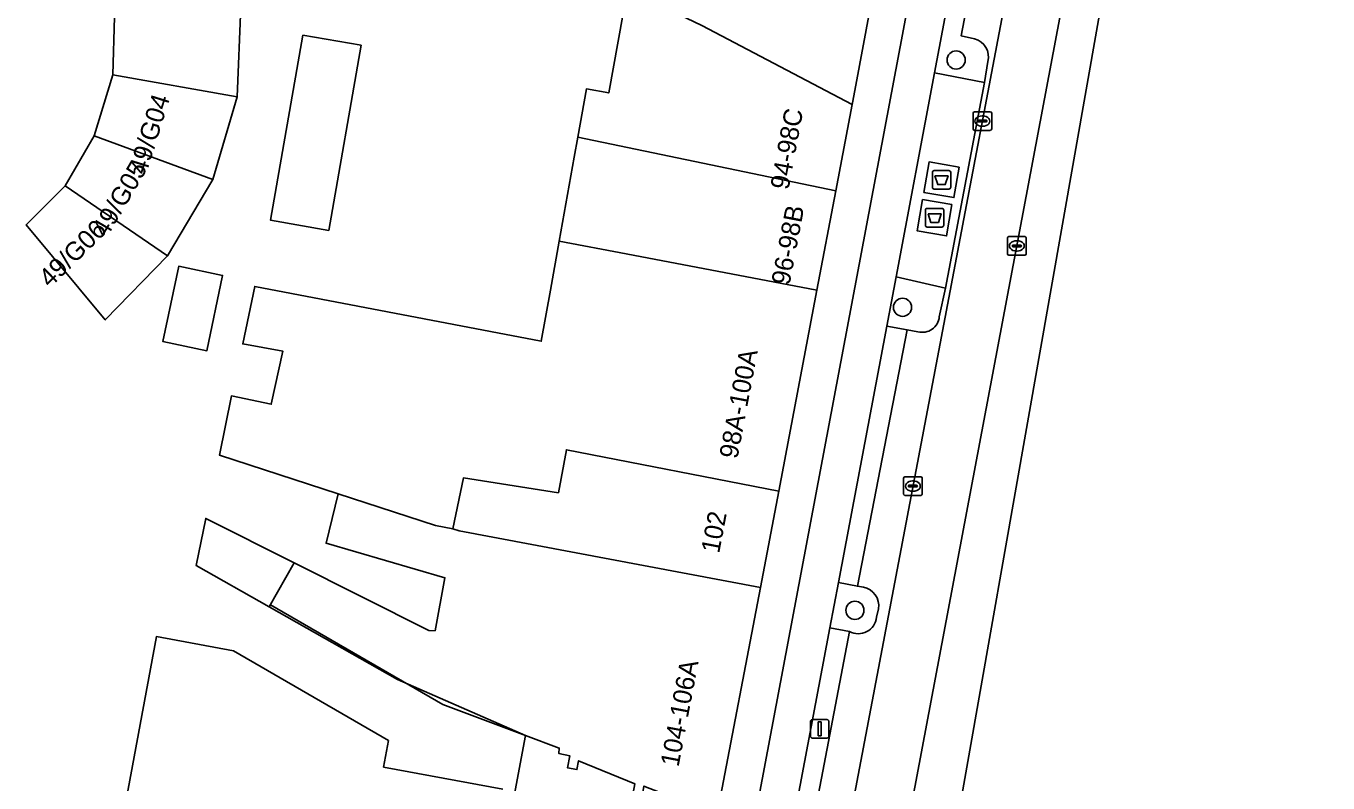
# Model space of a CAD drawing. Extents: x 161402 to 161933, y 381647 to 382315.
# Drawn here: x 161821 to 161891.1, y 381796.3 to 381837.1 of the extents above; entities that cross this region are included whole.
import ezdxf

# ---------------------------------------------------------------- set-up
doc = ezdxf.new("R2010")
doc.units = 0
for name, color, linetype in [('IMGEO_Afval_apart_plaats', 7, 'Continuous'), ('IMGEO_Berm_groen', 7, 'Continuous'), ('IMGEO_Berm_open', 7, 'Continuous'), ('IMGEO_Boom', 7, 'Continuous'), ('IMGEO_Erf', 7, 'Continuous'), ('IMGEO_Fietspad_gesloten', 7, 'Continuous'), ('IMGEO_Hek', 7, 'Continuous'), ('IMGEO_Kolk', 7, 'Continuous'), ('IMGEO_Lichtmast', 7, 'Continuous'), ('IMGEO_OVBaan_gesloten', 7, 'Continuous'), ('IMGEO_Pand', 7, 'Continuous'), ('IMGEO_Pand_nummerreeks', 7, 'Continuous'), ('IMGEO_Pand_overbouw', 7, 'Continuous'), ('IMGEO_Parkeervlak_open', 7, 'Continuous'), ('IMGEO_Rijbaan_lokaal_gesloten', 7, 'Continuous'), ('IMGEO_Rioolput', 7, 'Continuous'), ('IMGEO_Verkeerseiland_open', 7, 'Continuous'), ('IMGEO_Voetpad_gesloten', 7, 'Continuous'), ('IMGEO_Voetpad_open', 7, 'Continuous')]:
    doc.layers.add(name, color=color, linetype=linetype)

msp = doc.modelspace()

# ---------------------------------------------------------------- linework, layer by layer
at = {"layer": 'IMGEO_Afval_apart_plaats'}
for p, q in [((161869.774, 381828.434), (161869.774, 381829.234)), ((161869.774, 381829.234), (161869.774, 381828.434)), ((161869.874, 381829.334), (161870.664, 381829.334)), ((161870.664, 381829.334), (161869.874, 381829.334)), ((161870.764, 381829.234), (161870.764, 381828.434)), ((161870.764, 381828.434), (161870.764, 381829.234)), ((161870.664, 381828.334), (161869.874, 381828.334)), ((161869.874, 381828.334), (161870.664, 381828.334)), ((161869.4, 381826.391), (161869.4, 381827.191)), ((161869.4, 381827.191), (161869.4, 381826.391)), ((161869.5, 381827.291), (161870.29, 381827.291)), ((161870.29, 381827.291), (161869.5, 381827.291)), ((161870.39, 381827.191), (161870.39, 381826.391)), ((161870.39, 381826.391), (161870.39, 381827.191)), ((161870.29, 381826.291), (161869.5, 381826.291)), ((161869.5, 381826.291), (161870.29, 381826.291))]:
    msp.add_line(p, q, dxfattribs=at)
for points in [[(161869.917, 381829.048), (161870.621, 381829.048), (161870.472, 381828.578), (161870.066, 381828.578), (161869.917, 381829.048)], [(161869.543, 381827.005), (161870.247, 381827.005), (161870.098, 381826.535), (161869.692, 381826.535), (161869.543, 381827.005)]]:
    msp.add_lwpolyline(points, dxfattribs=at)
for centre, start, end in [((161869.874, 381829.234), 90, 180), ((161869.874, 381829.234), 90, 180), ((161870.664, 381829.234), 0, 90), ((161870.664, 381829.234), 360, 90), ((161869.874, 381828.434), 180, 270), ((161869.874, 381828.434), 180, 270), ((161870.664, 381828.434), 270, 0), ((161870.664, 381828.434), 270, 0), ((161869.5, 381827.191), 90, 180), ((161869.5, 381827.191), 90, 180), ((161870.29, 381827.191), 0, 90), ((161870.29, 381827.191), 360, 90), ((161869.5, 381826.391), 180, 270), ((161869.5, 381826.391), 180, 270), ((161870.29, 381826.391), 270, 0), ((161870.29, 381826.391), 270, 0)]:
    msp.add_arc(centre, 0.1, start, end, dxfattribs=at)
at = {"layer": 'IMGEO_Berm_groen'}
for points in [[(161870.482, 381822.992), (161867.824, 381823.608), (161867.323, 381820.954), (161868.41, 381820.749), (161868.995, 381820.652)], [(161870.147, 381821.456), (161870.482, 381822.992)], [(161866.06, 381806.892), (161865.742, 381806.939), (161864.714, 381807.133), (161864.254, 381804.698), (161865.316, 381804.498)], [(161866.768, 381805.264), (161866.881, 381805.727)]]:
    msp.add_lwpolyline(points, dxfattribs=at)
for centre, radius, start, end in [((161869.235, 381821.536), 0.916, 254.82541, 354.99825), ((161865.846, 381805.869), 1.045, 352.18385, 78.16247), ((161865.789, 381805.36), 0.983, 241.21658, 354.41103)]:
    msp.add_arc(centre, radius, start, end, dxfattribs=at)
at = {"layer": 'IMGEO_Berm_open'}
msp.add_lwpolyline([(161868.41, 381820.749), (161867.323, 381820.954), (161864.714, 381807.133), (161865.742, 381806.939)], close=True, dxfattribs=at)
msp.add_lwpolyline([(161855.069, 381750), (161856.164, 381755.911), (161857.682, 381764.091), (161858.781, 381770.01), (161859.554, 381774.178), (161860.503, 381779.34), (161860.529, 381779.475), (161865.316, 381804.498), (161864.254, 381804.698), (161859.509, 381779.56), (161854.016, 381750), (161850.643, 381731.85), (161849.541, 381725.922), (161844.249, 381697.445)], dxfattribs=at)
at = {"layer": 'IMGEO_Boom'}
for centre in [(161871.055, 381835.287), (161868.169, 381821.967), (161865.604, 381805.641)]:
    msp.add_circle(centre, 0.489, dxfattribs=at)
at = {"layer": 'IMGEO_Erf'}
for points in [[(161825.632, 381834.487), (161825.716, 381837.606), (161825.13, 381840.815), (161823.801, 381843.856), (161829.804, 381847.078), (161831.717, 381842.638), (161832.532, 381838.148), (161832.326, 381833.3), (161831.022, 381828.853), (161828.579, 381824.737), (161825.227, 381821.282), (161820.956, 381826.404), (161823.067, 381828.511), (161824.629, 381831.199)], [(161835.87, 381836.631), (161839.006, 381836.083), (161837.262, 381826.104), (161834.125, 381826.652)], [(161829.182, 381824.176), (161831.547, 381823.681), (161830.698, 381819.624), (161828.333, 381820.119)]]:
    msp.add_lwpolyline(points, close=True, dxfattribs=at)
for points in [[(161853.746, 381796.3), (161850.716, 381797.533), (161850.627, 381797.062), (161850.117, 381797.158), (161850.239, 381797.804), (161849.663, 381797.923), (161849.682, 381798.222), (161847.86, 381798.902), (161840.962, 381801.911), (161834.057, 381805.821), (161830.124, 381808.048), (161830.633, 381810.59), (161835.39, 381808.201), (161842.647, 381804.557), (161842.986, 381804.544), (161843.522, 381807.394), (161837.118, 381809.253), (161837.762, 381811.919), (161831.384, 381813.997), (161832.023, 381817.194), (161834.166, 381816.745), (161834.791, 381819.599), (161832.631, 381819.995), (161833.279, 381823.092), (161845.982, 381820.657), (161848.712, 381820.134), (161849.205, 381822.897), (161849.676, 381825.535), (161850.483, 381830.049), (161850.676, 381831.127), (161851.141, 381833.729), (161852.346, 381833.514), (161853.347, 381839.11)], [(161825.253, 381789.517), (161827.976, 381804.229), (161832.124, 381803.461), (161840.482, 381798.624), (161840.218, 381797.195), (161846.644, 381796.006)]]:
    msp.add_lwpolyline(points, dxfattribs=at)
at = {"layer": 'IMGEO_Fietspad_gesloten'}
for points in [[(161910.061, 382061.001), (161905.702, 382037.375), (161898.752, 382000), (161887.89, 381941.593), (161886.669, 381935.154), (161880.56, 381902.497), (161879.486, 381896.758), (161857.65, 381780.798), (161851.928, 381750), (161842.232, 381697.819)], [(161844.249, 381697.445), (161849.541, 381725.922), (161850.643, 381731.85), (161854.016, 381750), (161859.509, 381779.56), (161864.254, 381804.698), (161864.714, 381807.133), (161867.323, 381820.954), (161867.824, 381823.608), (161869.899, 381834.602), (161881.54, 381896.271)]]:
    msp.add_lwpolyline(points, dxfattribs=at)
at = {"layer": 'IMGEO_Hek'}
msp.add_lwpolyline([(161847.86, 381798.902), (161843.405, 381800.565), (161834.122, 381805.937)], dxfattribs=at)
at = {"layer": 'IMGEO_Kolk'}
for p, q in [((161871.971, 381831.573), (161871.971, 381832.425)), ((161872.046, 381832.499), (161872.898, 381832.499)), ((161872.23, 381831.993), (161872.23, 381832.005)), ((161872.668, 381831.956), (161872.27, 381831.956)), ((161872.273, 381832.042), (161872.671, 381832.042)), ((161872.459, 381832.279), (161872.484, 381832.279)), ((161872.714, 381832.005), (161872.714, 381831.993)), ((161872.972, 381832.425), (161872.972, 381831.573)), ((161872.898, 381831.499), (161872.046, 381831.499)), ((161872.482, 381831.719), (161872.457, 381831.719)), ((161868.225, 381811.906), (161868.225, 381812.758)), ((161868.3, 381812.832), (161869.152, 381812.832)), ((161868.484, 381812.326), (161868.484, 381812.338)), ((161868.922, 381812.289), (161868.524, 381812.289)), ((161868.527, 381812.375), (161868.925, 381812.375)), ((161868.713, 381812.612), (161868.738, 381812.612)), ((161868.968, 381812.338), (161868.968, 381812.326)), ((161869.226, 381812.758), (161869.226, 381811.906)), ((161869.152, 381811.832), (161868.3, 381811.832)), ((161868.736, 381812.052), (161868.711, 381812.052))]:
    msp.add_line(p, q, dxfattribs=at)
for points in [[(161871.971, 381831.573), (161871.971, 381832.425)], [(161872.046, 381832.499), (161872.898, 381832.499)], [(161872.972, 381832.425), (161872.972, 381831.573)], [(161872.898, 381831.499), (161872.046, 381831.499)], [(161868.225, 381811.906), (161868.225, 381812.758)], [(161868.3, 381812.832), (161869.152, 381812.832)], [(161869.226, 381812.758), (161869.226, 381811.906)], [(161869.152, 381811.832), (161868.3, 381811.832)]]:
    msp.add_lwpolyline(points, dxfattribs=at)
for centre, radius, start, end in [((161872.048, 381832.423), 0.0765, 91.55205, 178.44795), ((161872.048, 381832.423), 0.0765, 91.55205, 178.44795), ((161872.27, 381832.002), 0.0403, 85.87752, 175.75265), ((161872.267, 381831.992), 0.0366, 178.93798, 274.71019), ((161872.671, 381831.999), 0.043, 264.86636, 352.45326), ((161872.675, 381832.004), 0.0386, 1.73085, 96.63898), ((161872.896, 381832.423), 0.0765, 1.55205, 88.44795), ((161872.896, 381832.423), 0.0765, 1.55205, 88.44795), ((161872.048, 381831.575), 0.0765, 181.55205, 268.44795), ((161872.048, 381831.575), 0.0765, 181.55205, 268.44795), ((161872.896, 381831.575), 0.0765, 271.55205, 358.44795), ((161872.896, 381831.575), 0.0765, 271.55205, 358.44795), ((161868.302, 381812.756), 0.0765, 91.55205, 178.44795), ((161868.302, 381812.756), 0.0765, 91.55205, 178.44795), ((161868.524, 381812.335), 0.0403, 85.87752, 175.75265), ((161868.521, 381812.325), 0.0366, 178.93798, 274.71019), ((161868.925, 381812.332), 0.043, 264.86636, 352.45326), ((161868.929, 381812.337), 0.0386, 1.73085, 96.63898), ((161869.15, 381812.756), 0.0765, 1.55205, 88.44795), ((161869.15, 381812.756), 0.0765, 1.55205, 88.44795), ((161868.302, 381811.908), 0.0765, 181.55205, 268.44795), ((161868.302, 381811.908), 0.0765, 181.55205, 268.44795), ((161869.15, 381811.908), 0.0765, 271.55205, 358.44795), ((161869.15, 381811.908), 0.0765, 271.55205, 358.44795)]:
    msp.add_arc(centre, radius, start, end, dxfattribs=at)
for centre, major_axis, ratio, start_param, end_param in [((161872.458, 381831.999), (-0.387, 0.002), 0.722429, 4.712389, 7.853982), ((161872.483, 381831.999), (-0.39, 0.002), 0.717154, 1.570796, 4.712389), ((161868.712, 381812.332), (-0.387, 0.002), 0.722429, 4.712389, 7.853982), ((161868.737, 381812.332), (-0.39, 0.002), 0.717154, 1.570796, 4.712389)]:
    msp.add_ellipse(centre, major_axis=major_axis, ratio=ratio, start_param=start_param, end_param=end_param, dxfattribs=at)
at = {"layer": 'IMGEO_Lichtmast'}
for p, q in [((161863.21, 381798.856), (161863.21, 381799.656)), ((161863.21, 381799.656), (161863.21, 381798.856)), ((161863.31, 381799.756), (161864.1, 381799.756)), ((161864.1, 381799.756), (161863.31, 381799.756)), ((161864.2, 381799.656), (161864.2, 381798.856)), ((161864.2, 381798.856), (161864.2, 381799.656)), ((161864.1, 381798.756), (161863.31, 381798.756)), ((161863.31, 381798.756), (161864.1, 381798.756))]:
    msp.add_line(p, q, dxfattribs=at)
msp.add_lwpolyline([(161863.63, 381799.631), (161863.78, 381799.631), (161863.78, 381798.881), (161863.63, 381798.881), (161863.63, 381799.631)], dxfattribs=at)
for centre, start, end in [((161863.31, 381799.656), 90, 180), ((161863.31, 381799.656), 90, 180), ((161864.1, 381799.656), 0, 90), ((161864.1, 381799.656), 360, 90), ((161863.31, 381798.856), 180, 270), ((161863.31, 381798.856), 180, 270), ((161864.1, 381798.856), 270, 0), ((161864.1, 381798.856), 270, 0)]:
    msp.add_arc(centre, 0.1, start, end, dxfattribs=at)
at = {"layer": 'IMGEO_OVBaan_gesloten'}
for points in [[(161847.327, 381677.629), (161847.814, 381679.325), (161869.795, 381786.79), (161883.773, 381866.122), (161911.481, 382007.357), (161916.93, 382035.129), (161933.101, 382124.399), (161931.462, 382125.963), (161930.949, 382121.39)], [(161929.574, 382113.249), (161927.659, 382104.365), (161926.989, 382101.276), (161926.695, 382099.95), (161920.797, 382074.121), (161920.568, 382072.989), (161920.066, 382070.485), (161894.174, 381930.698), (161894.155, 381930.593), (161893.956, 381929.536), (161893.492, 381927.072), (161889.963, 381908.334), (161866.208, 381782.197), (161866.199, 381782.149), (161865.069, 381776.053), (161864.537, 381773.18), (161864.311, 381771.961), (161856.328, 381728.885)]]:
    msp.add_lwpolyline(points, dxfattribs=at)
at = {"layer": 'IMGEO_Pand'}
for points in [[(161871.236, 381863.835), (161860.337, 381865.887), (161860.582, 381867.192), (161858.508, 381867.582), (161853.371, 381868.549), (161853.071, 381866.952), (161852.795, 381867.004), (161848.503, 381844.194), (161848.012, 381841.585), (161848.885, 381841.123), (161848.95, 381841.485), (161852.213, 381839.723), (161853.347, 381839.11), (161853.718, 381838.91), (161857.352, 381837.151), (161865.464, 381832.9), (161865.498, 381833.078)], [(161857.352, 381837.151), (161853.718, 381838.91), (161853.347, 381839.11), (161852.346, 381833.514), (161851.141, 381833.729), (161850.676, 381831.127), (161864.577, 381828.237), (161865.464, 381832.9)], [(161832.326, 381833.3), (161832.532, 381838.148), (161825.716, 381837.606), (161825.632, 381834.487)], [(161835.87, 381836.631), (161834.125, 381826.652), (161837.262, 381826.104), (161839.006, 381836.083)], [(161832.326, 381833.3), (161825.632, 381834.487), (161824.629, 381831.199), (161831.022, 381828.853)], [(161831.022, 381828.853), (161824.629, 381831.199), (161823.067, 381828.511), (161828.579, 381824.737)], [(161864.577, 381828.237), (161850.676, 381831.127), (161850.483, 381830.049), (161849.676, 381825.535), (161853.274, 381824.851), (161863.56, 381822.895)], [(161823.067, 381828.511), (161820.956, 381826.404), (161825.227, 381821.282), (161828.579, 381824.737)], [(161863.56, 381822.895), (161853.274, 381824.851), (161849.676, 381825.535), (161849.205, 381822.897), (161848.712, 381820.134), (161845.982, 381820.657), (161833.279, 381823.092), (161832.631, 381819.995), (161834.791, 381819.599), (161834.166, 381816.745), (161832.023, 381817.194), (161831.384, 381813.997), (161837.762, 381811.919), (161843.015, 381810.207), (161843.941, 381810.032), (161844.516, 381812.77), (161849.633, 381811.975), (161850.068, 381814.292), (161861.5, 381812.067)], [(161828.333, 381820.119), (161830.698, 381819.624), (161831.547, 381823.681), (161829.182, 381824.176)], [(161843.941, 381810.032), (161844.279, 381809.92), (161860.511, 381806.869), (161861.5, 381812.067), (161850.068, 381814.292), (161849.633, 381811.975), (161844.516, 381812.77)], [(161830.633, 381810.59), (161830.124, 381808.048), (161834.057, 381805.821), (161835.39, 381808.201)]]:
    msp.add_lwpolyline(points, close=True, dxfattribs=at)
for points in [[(161858.21, 381794.775), (161860.511, 381806.869), (161844.279, 381809.92), (161843.941, 381810.032), (161843.015, 381810.207), (161837.762, 381811.919), (161837.118, 381809.253), (161843.522, 381807.394), (161842.986, 381804.544), (161842.647, 381804.557), (161835.39, 381808.201), (161834.057, 381805.821), (161840.962, 381801.911), (161847.86, 381798.902), (161849.682, 381798.222), (161849.663, 381797.923), (161850.239, 381797.804), (161850.117, 381797.158), (161850.627, 381797.062), (161850.716, 381797.533), (161853.746, 381796.3)], [(161846.644, 381796.006), (161840.218, 381797.195), (161840.482, 381798.624), (161832.124, 381803.461), (161827.976, 381804.229), (161825.253, 381789.517)]]:
    msp.add_lwpolyline(points, dxfattribs=at)
at = {"layer": 'IMGEO_Pand_overbouw'}
msp.add_lwpolyline([(161857.009, 381789.446), (161858.115, 381794.262), (161857.427, 381794.392), (161857.521, 381794.895), (161854.239, 381796.167), (161854.154, 381795.713), (161853.653, 381795.807), (161853.746, 381796.3), (161850.716, 381797.533), (161850.627, 381797.062), (161850.117, 381797.158), (161850.239, 381797.804), (161849.663, 381797.923), (161849.682, 381798.222), (161847.86, 381798.902), (161847.248, 381795.649), (161851.239, 381794.077), (161851.163, 381793.987), (161851.433, 381793.88), (161856.08, 381792.037), (161856.9, 381790.844), (161856.653, 381789.512)], close=True, dxfattribs=at)
at = {"layer": 'IMGEO_Parkeervlak_open'}
for points in [[(161865.316, 381804.498), (161860.529, 381779.475), (161861.521, 381781.789), (161862.376, 381783.945), (161863.081, 381785.029), (161863.613, 381786.178), (161864.093, 381787.863), (161884.15, 381893.504)], [(161873.66, 381847.251), (161873.371, 381847.295), (161871.323, 381836.592), (161872.047, 381836.423)], [(161872.769, 381835.211), (161872.587, 381834.08), (161870.482, 381822.992), (161870.147, 381821.456)], [(161868.995, 381820.652), (161868.41, 381820.749), (161865.742, 381806.939), (161866.06, 381806.892)], [(161866.881, 381805.727), (161866.768, 381805.264)]]:
    msp.add_lwpolyline(points, dxfattribs=at)
for centre, radius, start, end in [((161871.795, 381835.452), 1.004, 346.1316, 75.43372), ((161869.235, 381821.536), 0.916, 254.82541, 354.99825), ((161865.846, 381805.869), 1.045, 352.18385, 78.16247), ((161865.789, 381805.36), 0.983, 241.21658, 354.41103)]:
    msp.add_arc(centre, radius, start, end, dxfattribs=at)
at = {"layer": 'IMGEO_Rijbaan_lokaal_gesloten'}
for points in [[(161866.208, 381782.197), (161889.963, 381908.334)], [(161884.17, 381893.607), (161884.15, 381893.504), (161864.093, 381787.863), (161863.613, 381786.178), (161863.081, 381785.029), (161862.376, 381783.945), (161861.521, 381781.789), (161860.529, 381779.475), (161860.503, 381779.34), (161859.554, 381774.178), (161858.781, 381770.01), (161857.682, 381764.091), (161856.164, 381755.911), (161855.069, 381750), (161851.669, 381731.66), (161850.569, 381725.731), (161845.879, 381700.449), (161845.656, 381699.227), (161845.077, 381696.29), (161841.891, 381681.821), (161841.621, 381680.659), (161841.162, 381678.679), (161840.43, 381675.643), (161840.392, 381675.483)]]:
    msp.add_lwpolyline(points, dxfattribs=at)
at = {"layer": 'IMGEO_Rioolput'}
for p, q in [((161873.826, 381824.847), (161873.826, 381825.699)), ((161873.901, 381825.773), (161874.753, 381825.773)), ((161874.314, 381825.553), (161874.339, 381825.553)), ((161874.827, 381825.699), (161874.827, 381824.847)), ((161874.085, 381825.267), (161874.085, 381825.279)), ((161874.523, 381825.23), (161874.125, 381825.23)), ((161874.128, 381825.316), (161874.526, 381825.316)), ((161874.337, 381824.993), (161874.312, 381824.993)), ((161874.569, 381825.279), (161874.569, 381825.267)), ((161874.753, 381824.773), (161873.901, 381824.773))]:
    msp.add_line(p, q, dxfattribs=at)
for points in [[(161873.826, 381824.847), (161873.826, 381825.699)], [(161873.901, 381825.773), (161874.753, 381825.773)], [(161874.827, 381825.699), (161874.827, 381824.847)], [(161874.753, 381824.773), (161873.901, 381824.773)]]:
    msp.add_lwpolyline(points, dxfattribs=at)
for centre, radius, start, end in [((161873.903, 381825.697), 0.0765, 91.55205, 178.44795), ((161873.903, 381825.697), 0.0765, 91.55205, 178.44795), ((161874.751, 381825.697), 0.0765, 1.55205, 88.44795), ((161874.751, 381825.697), 0.0765, 1.55205, 88.44795), ((161873.903, 381824.849), 0.0765, 181.55205, 268.44795), ((161873.903, 381824.849), 0.0765, 181.55205, 268.44795), ((161874.125, 381825.276), 0.0403, 85.87752, 175.75265), ((161874.122, 381825.266), 0.0366, 178.93798, 274.71019), ((161874.526, 381825.273), 0.043, 264.86636, 352.45326), ((161874.53, 381825.278), 0.0386, 1.73085, 96.63898), ((161874.751, 381824.849), 0.0765, 271.55205, 358.44795), ((161874.751, 381824.849), 0.0765, 271.55205, 358.44795)]:
    msp.add_arc(centre, radius, start, end, dxfattribs=at)
for centre, major_axis, ratio, start_param, end_param in [((161874.313, 381825.273), (-0.387, 0.002), 0.722429, 4.712389, 7.853982), ((161874.338, 381825.273), (-0.39, 0.002), 0.717154, 1.570796, 4.712389)]:
    msp.add_ellipse(centre, major_axis=major_axis, ratio=ratio, start_param=start_param, end_param=end_param, dxfattribs=at)
at = {"layer": 'IMGEO_Verkeerseiland_open'}
for points in [[(161912.039, 382060.567), (161908.061, 382038.88), (161900.83, 382000), (161890.059, 381942.083), (161888.398, 381933.147), (161882.623, 381902.093), (161881.54, 381896.271), (161869.899, 381834.602), (161872.587, 381834.08), (161872.769, 381835.211)], [(161872.047, 381836.423), (161871.323, 381836.592), (161873.371, 381847.295), (161873.66, 381847.251)]]:
    msp.add_lwpolyline(points, dxfattribs=at)
msp.add_arc((161871.795, 381835.452), 1.004, 346.1316, 75.43372, dxfattribs=at)
at = {"layer": 'IMGEO_Voetpad_gesloten'}
for points in [[(161871.222, 381829.513), (161869.6, 381829.794), (161869.316, 381828.156), (161870.938, 381827.875)], [(161870.826, 381827.506), (161869.246, 381827.769), (161868.964, 381826.077), (161870.544, 381825.814)]]:
    msp.add_lwpolyline(points, close=True, dxfattribs=at)
at = {"layer": 'IMGEO_Voetpad_open'}
for points in [[(161842.232, 381697.819), (161851.928, 381750), (161857.65, 381780.798), (161879.486, 381896.758)], [(161874.777, 381882.317), (161872.114, 381868.466), (161871.236, 381863.835), (161865.498, 381833.078), (161865.464, 381832.9), (161864.577, 381828.237), (161863.56, 381822.895), (161861.5, 381812.067), (161860.511, 381806.869), (161858.21, 381794.775)]]:
    msp.add_lwpolyline(points, dxfattribs=at)
for points in [[(161872.587, 381834.08), (161869.899, 381834.602), (161867.824, 381823.608), (161870.482, 381822.992)], [(161871.222, 381829.513), (161870.938, 381827.875), (161869.316, 381828.156), (161869.6, 381829.794)], [(161870.826, 381827.506), (161870.544, 381825.814), (161868.964, 381826.077), (161869.246, 381827.769)]]:
    msp.add_lwpolyline(points, close=True, dxfattribs=at)

# ---------------------------------------------------------------- texts
at = {"layer": 'IMGEO_Pand_nummerreeks'}
for s, rotation, p in [('49/G04', 72.64598, (161827.413, 381829.06)), ('94-98C', 79.45206, (161862.022, 381828.258)), ('49/G05', 59.53446, (161825.298, 381825.671)), ('96-98B', 79.22287, (161862.075, 381823.116)), ('49/G06', 44.46454, (161822.24, 381822.983)), ('98A-100A', 79.2859, (161859.271, 381813.764)), ('102', 79.22735, (161858.289, 381808.672)), ('104-106A', 79.2286, (161856.101, 381797.17))]:
    msp.add_text(s, height=1, rotation=rotation, dxfattribs=at).set_placement(p)

doc.saveas('drawing.dxf')
